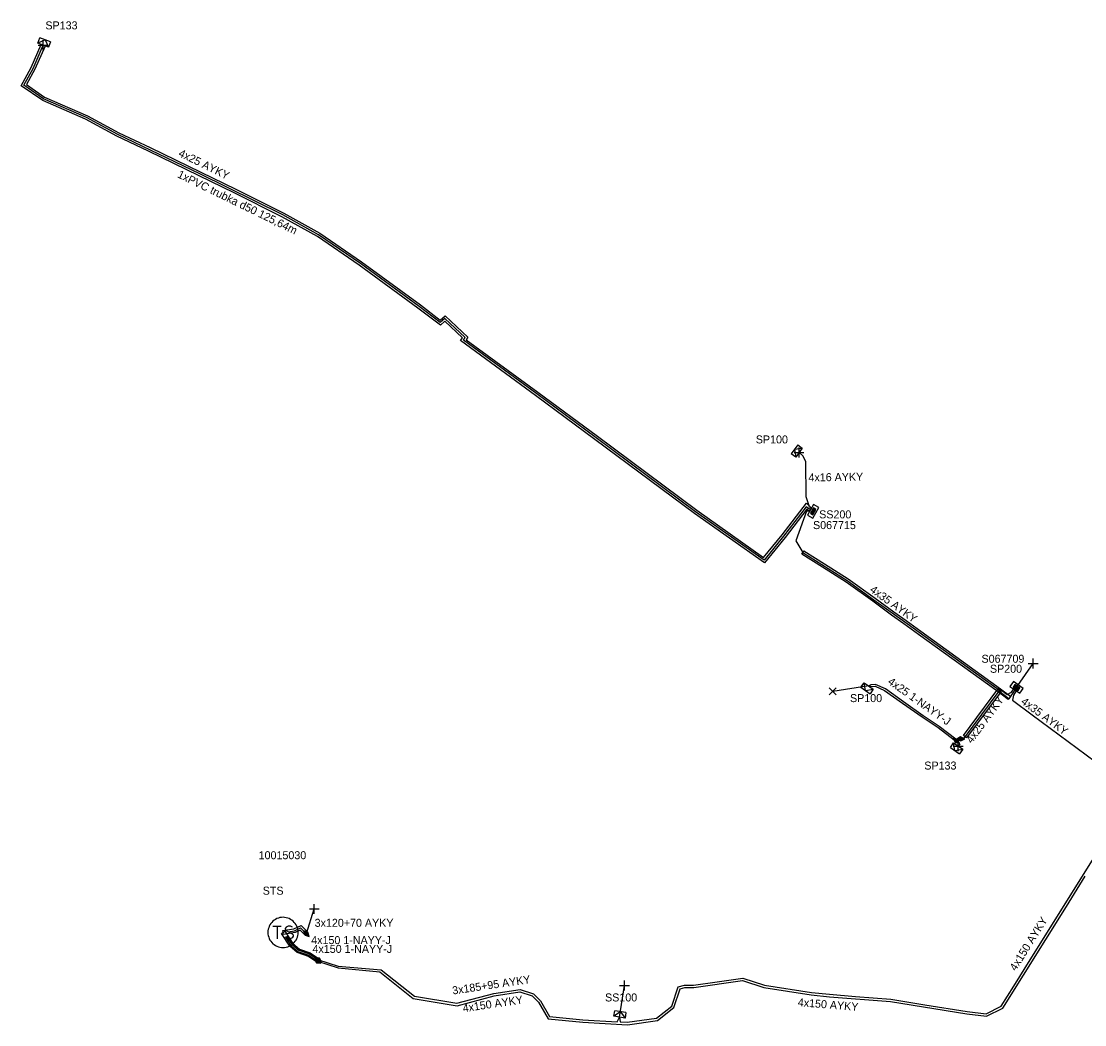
# Model space of a CAD drawing. Extents: x -737417 to -734469, y -1145580 to -1142703.
# Drawn here: x -737058.1 to -736925.2, y -1144906.3 to -1144780.8 of the extents above; entities that cross this region are included whole.
import ezdxf

# ---------------------------------------------------------------- set-up
doc = ezdxf.new("R2010")
doc.units = 0
for name, color, linetype in [('Vrstva 1', 7, 'Continuous'), ('Vrstva 19', 7, 'Continuous'), ('Vrstva 20', 7, 'Continuous'), ('Vrstva 21', 7, 'Continuous'), ('Vrstva 25', 7, 'Continuous'), ('Vrstva 26', 7, 'Continuous'), ('Vrstva 27', 7, 'Continuous'), ('Vrstva 28', 7, 'Continuous'), ('Vrstva 29', 7, 'Continuous'), ('Vrstva 30', 7, 'Continuous'), ('Vrstva 31', 7, 'Continuous'), ('Vrstva 33', 7, 'Continuous'), ('Vrstva 34', 7, 'Continuous'), ('Vrstva 4', 7, 'Continuous'), ('Vrstva 5', 7, 'Continuous'), ('Vrstva 52', 7, 'Continuous'), ('Vrstva 54', 7, 'Continuous'), ('Vrstva 59', 7, 'Continuous'), ('Vrstva 6', 7, 'Continuous'), ('Vrstva 8', 7, 'Continuous'), ('Vrstva 9', 7, 'Continuous')]:
    doc.layers.add(name, color=color, linetype=linetype)

# ---------------------------------------------------------------- blocks, each defined once
blk = doc.blocks.new('NN870')
at = {"layer": 'Vrstva 4'}
for points in [[(0, -0.25), (0.5, 0), (0, 0.25), (-0.5, 0), (0, -0.25)], [(0.37, 0), (0, 0.19), (-0.36, 0), (0, -0.19), (0.37, 0)], [(0.24, 0), (0, 0.12), (-0.25, 0), (0, -0.12), (0.24, 0)], [(0.12, 0), (0, 0.06), (-0.13, 0), (0, -0.06), (0.12, 0)]]:
    blk.add_lwpolyline(points, dxfattribs=at)
blk = doc.blocks.new('NN800')
at = {"layer": 'Vrstva 1'}
for points in [[(-0.44, 0.44), (0.44, -0.44)], [(-0.44, -0.44), (0.44, 0.44)]]:
    blk.add_lwpolyline(points, dxfattribs=at)
blk = doc.blocks.new('NN620')
at = {"layer": 'Vrstva 8'}
for points in [[(0.75, 0), (-0.75, 0)], [(-0.75, 0), (-0.75, -0.75)], [(0.75, -0.75), (0.75, 0)], [(-0.75, -0.75), (0.75, -0.75)], [(0.37, -0.18), (-0.38, -0.18)], [(-0.38, -0.18), (-0.38, -0.56)], [(-0.38, -0.56), (0.37, -0.56)], [(0.32, -0.23), (-0.33, -0.23)], [(-0.33, -0.23), (-0.33, -0.51)], [(-0.33, -0.51), (0.32, -0.51)], [(0.27, -0.27), (-0.28, -0.27)], [(-0.28, -0.27), (-0.28, -0.46)], [(-0.28, -0.46), (0.27, -0.46)], [(0.23, -0.32), (-0.23, -0.32)], [(-0.23, -0.32), (-0.23, -0.42)], [(-0.23, -0.42), (0.23, -0.42)], [(-0.19, -0.37), (0.19, -0.37)], [(0.23, -0.42), (0.23, -0.32)], [(0.27, -0.46), (0.27, -0.27)], [(0.32, -0.51), (0.32, -0.23)], [(0.37, -0.56), (0.37, -0.18)]]:
    blk.add_lwpolyline(points, dxfattribs=at)
blk = doc.blocks.new('NN630')
at = {"layer": 'Vrstva 9'}
for points in [[(0, -0.7), (-0.7, 0)], [(-0.7, -0.7), (-0.7, 0), (0.7, 0), (0.7, -0.7)], [(-0.7, -0.7), (0.7, -0.7)], [(0, -0.7), (0.7, 0)]]:
    blk.add_lwpolyline(points, dxfattribs=at)
blk = doc.blocks.new('NN610')
at = {"layer": 'Vrstva 6'}
for points in [[(1.88, 0), (1.87, 0.2), (1.84, 0.39), (1.79, 0.58), (1.72, 0.77), (1.63, 0.94), (1.52, 1.11), (1.4, 1.26), (1.26, 1.4), (1.1, 1.53), (0.94, 1.63), (0.76, 1.72), (0.58, 1.8), (0.19, 1.88), (0.19, 1.88), (-0.01, 1.89), (-0.21, 1.88), (-0.4, 1.85), (-0.59, 1.8), (-0.78, 1.72), (-0.95, 1.63), (-1.12, 1.53), (-1.27, 1.4), (-1.41, 1.26), (-1.54, 1.11), (-1.64, 0.94), (-1.73, 0.77), (-1.8, 0.58), (-1.86, 0.39), (-1.89, 0.2), (-1.9, 0), (-1.89, -0.2), (-1.86, -0.39), (-1.8, -0.58), (-1.73, -0.77), (-1.64, -0.95), (-1.54, -1.11), (-1.41, -1.27), (-1.27, -1.41), (-1.12, -1.53), (-0.95, -1.64), (-0.78, -1.73), (-0.59, -1.8), (-0.4, -1.85), (-0.21, -1.88), (-0.01, -1.89), (0.19, -1.88), (0.39, -1.85), (0.58, -1.8), (0.76, -1.73), (0.94, -1.64), (1.1, -1.53), (1.26, -1.41), (1.4, -1.27), (1.52, -1.11), (1.63, -0.95), (1.72, -0.77), (1.79, -0.58), (1.84, -0.39), (1.87, -0.2), (1.88, 0)], [(-1.27, 0.78), (-0.26, 0.78)], [(-0.76, 0.78), (-0.76, -0.79)], [(1.19, 0.66), (0.94, 0.78), (0.62, 0.78), (0.37, 0.66), (0.24, 0.47), (0.24, 0.4), (0.37, 0.22), (1.12, -0.16), (1.25, -0.32), (1.25, -0.48), (1.12, -0.67), (0.87, -0.79), (0.62, -0.79), (0.49, -0.73), (0.24, -0.6)]]:
    blk.add_lwpolyline(points, dxfattribs=at)

msp = doc.modelspace()

# ---------------------------------------------------------------- linework, layer by layer
at = {"layer": 'Vrstva 20'}
for points in [[(-736959.58, -1144842.09), (-736959.88, -1144841.81), (-736962.58, -1144845.36), (-736965.18, -1144848.54), (-736973.94, -1144842.35), (-736986.36, -1144833.11), (-736993.8, -1144827.6), (-737003.15, -1144820.76), (-737002.92, -1144820.42), (-737005.12, -1144818.34), (-737005.69, -1144818.83), (-737008.49, -1144816.69), (-737015.82, -1144811.32), (-737021.03, -1144807.75), (-737025.51, -1144805.27), (-737031.45, -1144802.28), (-737035.85, -1144800.14), (-737042.18, -1144797.06), (-737046.11, -1144795.22), (-737050.02, -1144793.09), (-737055.39, -1144790.75), (-737058.07, -1144788.91), (-737056.83, -1144786.62), (-737055.56, -1144783.73), (-737055.1, -1144783.93), (-737056.38, -1144786.84), (-737057.41, -1144788.75), (-737055.15, -1144790.31), (-737049.8, -1144792.65), (-737045.89, -1144794.78), (-737041.96, -1144796.6), (-737035.63, -1144799.69), (-737031.23, -1144801.84), (-737025.27, -1144804.83), (-737020.77, -1144807.33), (-737015.53, -1144810.92), (-737008.19, -1144816.29), (-737005.71, -1144818.19), (-737005.1, -1144817.68), (-737002.26, -1144820.34), (-737002.47, -1144820.64), (-736993.5, -1144827.2), (-736986.06, -1144832.71), (-736973.64, -1144841.95), (-736965.28, -1144847.86), (-736962.98, -1144845.05), (-736959.94, -1144841.07), (-736959.24, -1144841.73)], [(-736960.52, -1144847.47), (-736960.26, -1144847.05), (-736957.67, -1144848.67), (-736954.7, -1144850.54), (-736951.36, -1144852.94), (-736949, -1144854.66), (-736947.45, -1144855.76), (-736945.62, -1144857.1), (-736935.66, -1144864.27), (-736934.4, -1144865.24), (-736934.7, -1144865.64), (-736935.96, -1144864.67), (-736945.91, -1144857.51), (-736947.74, -1144856.17), (-736949.29, -1144855.07), (-736951.65, -1144853.34), (-736954.98, -1144850.96), (-736957.94, -1144849.09)], [(-736939.91, -1144870.42), (-736940.31, -1144870.12), (-736936.01, -1144864.32), (-736935.61, -1144864.62)], [(-737025.13, -1144894.6), (-737024.11, -1144896.13), (-737023.31, -1144896.83), (-737021.96, -1144897.28), (-737020.84, -1144898.04), (-737021.12, -1144898.46), (-737022.18, -1144897.74), (-737023.57, -1144897.27), (-737024.49, -1144896.47), (-737025.55, -1144894.88)], [(-737025.38, -1144894.49), (-737023.98, -1144894.29), (-737023.1, -1144893.86), (-737022.24, -1144894.71), (-737022.6, -1144895.07), (-737023.2, -1144894.46), (-737023.82, -1144894.77), (-737025.3, -1144894.99)]]:
    msp.add_lwpolyline(points, close=True, dxfattribs=at)
at = {"layer": 'Vrstva 5'}
for points in [[(-736959.51, -1144842.09), (-736959.91, -1144842.09), (-736961.24, -1144845.8), (-736960.39, -1144847.26), (-736954.84, -1144850.75), (-736951.52, -1144853.15), (-736947.36, -1144856.14), (-736936.11, -1144864.25), (-736935.72, -1144864.35), (-736934.86, -1144865.01), (-736934.32, -1144864.69), (-736934.01, -1144864.31)], [(-736940.65, -1144870.56), (-736941.26, -1144870.58), (-736943.34, -1144868.98), (-736945.34, -1144867.65), (-736947.79, -1144865.92), (-736950.06, -1144864.3), (-736951.3, -1144863.74), (-736951.87, -1144863.8), (-736952.14, -1144863.93), (-736951.73, -1144863.98), (-736951.34, -1144863.94), (-736950.16, -1144864.48), (-736947.91, -1144866.08), (-736945.46, -1144867.81), (-736943.46, -1144869.14), (-736941.48, -1144870.66), (-736941.19, -1144870.79)], [(-736933.88, -1144864.42), (-736934.64, -1144865.56), (-736935.9, -1144864.59), (-736940.21, -1144870.42), (-736940.65, -1144870.56)], [(-736933.7, -1144864.52), (-736934.04, -1144865.07), (-736934.19, -1144865.71), (-736931.73, -1144867.53), (-736921.6, -1144875.04), (-736919.22, -1144874.32), (-736920.26, -1144873.68)], [(-736983.3, -1144905.34), (-736983.2, -1144905.93), (-736982.33, -1144905.98), (-736978.66, -1144905.48), (-736976.75, -1144903.94), (-736975.96, -1144901.54), (-736975.18, -1144901.33), (-736974.04, -1144901.32), (-736971.1, -1144900.91), (-736967.89, -1144900.45), (-736965.19, -1144901.34), (-736959.29, -1144902.26), (-736957.04, -1144902.48), (-736953.8, -1144902.74), (-736949.38, -1144903.09), (-736945.14, -1144903.78), (-736939.83, -1144904.63), (-736937.49, -1144904.9), (-736935.59, -1144903.96), (-736934.03, -1144901.45), (-736931.98, -1144898.17), (-736923.56, -1144884.72)], [(-737021.04, -1144898.33), (-737018.47, -1144899.18), (-737013.27, -1144899.65), (-737009.1, -1144902.99), (-737003.6, -1144903.9), (-736998.95, -1144902.66), (-736995.75, -1144902.18), (-736994.21, -1144902.67), (-736993.43, -1144903.48), (-736992.21, -1144905.55), (-736987.88, -1144905.98), (-736982.31, -1144906.28), (-736978.54, -1144905.76), (-736976.49, -1144904.12), (-736975.72, -1144901.78), (-736975.14, -1144901.63), (-736974.02, -1144901.62), (-736967.91, -1144900.75), (-736965.26, -1144901.64), (-736959.33, -1144902.56), (-736957.06, -1144902.78), (-736949.42, -1144903.39), (-736939.87, -1144904.93), (-736937.43, -1144905.2), (-736935.38, -1144904.19), (-736927.44, -1144891.48), (-736925.09, -1144887.72)], [(-737024.69, -1144894.65), (-737023.9, -1144894.53), (-737023.15, -1144894.16), (-737022.42, -1144894.89)], [(-737025.06, -1144895.34), (-737024.38, -1144896.37), (-737023.49, -1144897.14), (-737022.11, -1144897.6), (-737021.04, -1144898.33)], [(-737024.9, -1144895.22), (-737024.22, -1144896.23), (-737023.39, -1144896.96), (-737022.03, -1144897.42), (-737020.92, -1144898.17)], [(-737020.92, -1144898.17), (-737018.44, -1144898.95), (-737013.08, -1144899.4), (-737008.94, -1144902.71), (-737003.62, -1144903.6), (-736999.01, -1144902.36), (-736995.73, -1144901.88), (-736994.05, -1144902.41), (-736993.19, -1144903.3), (-736992.03, -1144905.27), (-736987.86, -1144905.68), (-736983.59, -1144905.9), (-736983.3, -1144905.34)]]:
    msp.add_lwpolyline(points, dxfattribs=at)
at = {"layer": 'Vrstva 52'}
for points in [[(-736959.41, -1144841.91), (-736959.97, -1144841.52), (-736962.78, -1144845.21), (-736965.23, -1144848.2), (-736973.79, -1144842.15), (-736986.21, -1144832.91), (-736993.65, -1144827.4), (-737002.81, -1144820.7), (-737002.59, -1144820.38), (-737005.11, -1144818.01), (-737005.7, -1144818.51), (-737008.34, -1144816.49), (-737015.67, -1144811.12), (-737020.9, -1144807.54), (-737025.39, -1144805.05), (-737035.74, -1144799.91), (-737046, -1144795), (-737049.91, -1144792.87), (-737055.27, -1144790.53), (-737057.74, -1144788.83), (-737056.6, -1144786.73), (-737055.33, -1144783.83)], [(-736959.29, -1144841.77), (-736959.54, -1144841.53), (-736959.95, -1144840.27), (-736960.02, -1144835.88), (-736960.38, -1144835.18), (-736960.86, -1144834.75)], [(-736941.19, -1144870.79), (-736940.77, -1144871.17), (-736940.97, -1144871.44)]]:
    msp.add_lwpolyline(points, dxfattribs=at)
at = {"layer": 'Vrstva 59'}
for points in [[(-736933.5, -1144863.87), (-736931.61, -1144861.13)], [(-736952.14, -1144863.93), (-736956.65, -1144864.62)], [(-737022.42, -1144894.89), (-737021.44, -1144891.81)], [(-736983.3, -1144905.34), (-736982.66, -1144901.39)]]:
    msp.add_lwpolyline(points, dxfattribs=at)

# ---------------------------------------------------------------- block references
at = {"layer": 'Vrstva 19'}
for p, rotation in [((-736941.19, -1144870.79), -37.77717136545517), ((-736940.65, -1144870.56), 3.47376526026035), ((-737022.42, -1144894.89), -45.282485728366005), ((-737020.95, -1144898.15), -34.923701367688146), ((-737021.04, -1144898.33), -32.93533191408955)]:
    msp.add_blockref('NN870', p, dxfattribs=dict(at, rotation=rotation))
at = {"layer": 'Vrstva 25'}
msp.add_blockref('NN610', (-737025.34, -1144894.74), dxfattribs=at)
at = {"layer": 'Vrstva 28'}
for p, rotation in [((-736959.41, -1144841.91), 60.12400841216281), ((-736933.88, -1144864.42), 145.43059169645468)]:
    msp.add_blockref('NN620', p, dxfattribs=dict(at, rotation=rotation))
at = {"layer": 'Vrstva 31'}
for p, rotation in [((-737055.33, -1144783.83), 159.20128886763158), ((-736960.86, -1144834.75), -126.19320829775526), ((-736952.14, -1144863.93), -35.90344366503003), ((-736940.97, -1144871.44), -34.53349169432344), ((-736983.3, -1144905.34), 170.8518527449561)]:
    msp.add_blockref('NN630', p, dxfattribs=dict(at, rotation=rotation))
at = {"layer": 'Vrstva 34'}
for p, rotation in [((-737055.33, -1144783.83), 45), ((-736960.86, -1144834.75), 45), ((-736931.61, -1144861.13), 45), ((-736940.97, -1144871.44), 45.00000009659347), ((-737021.44, -1144891.81), 45), ((-736982.66, -1144901.39), 45)]:
    msp.add_blockref('NN800', p, dxfattribs=dict(at, rotation=rotation))
msp.add_blockref('NN800', (-736956.65, -1144864.62), dxfattribs=at)

# ---------------------------------------------------------------- texts
at = {"layer": 'Vrstva 21'}
msp.add_text('1xPVC trubka d50 125,64m', height=1, rotation=333.958, dxfattribs=at).set_placement((-737038.64, -1144800.31))
at = {"layer": 'Vrstva 26'}
msp.add_text('10015030', height=1, dxfattribs=at).set_placement((-737028.4, -1144885.59))
at = {"layer": 'Vrstva 27'}
msp.add_text('STS', height=1, dxfattribs=at).set_placement((-737027.89, -1144890.02))
at = {"layer": 'Vrstva 29'}
for s, p in [('S067715', (-736959.11, -1144844.32)), ('S067709', (-736938.05, -1144861.03))]:
    msp.add_text(s, height=1, dxfattribs=at).set_placement(p)
at = {"layer": 'Vrstva 30'}
for s, p in [('SS200', (-736958.34, -1144842.98)), ('SP200', (-736937, -1144862.28))]:
    msp.add_text(s, height=1, dxfattribs=at).set_placement(p)
at = {"layer": 'Vrstva 33'}
for s, p in [('SP133', (-737055.05, -1144781.85)), ('SP100', (-736966.26, -1144833.61)), ('SP100', (-736954.49, -1144865.95)), ('SP133', (-736945.2, -1144874.38)), ('SS100', (-736985.1, -1144903.37))]:
    msp.add_text(s, height=1, dxfattribs=at).set_placement(p)
at = {"layer": 'Vrstva 54'}
for s, rotation, p in [('4x25 AYKY', 333.964, (-737038.51, -1144797.66)), ('4x16 AYKY', 0.914, (-736959.67, -1144838.37))]:
    msp.add_text(s, height=1, rotation=rotation, dxfattribs=at).set_placement(p)
at = {"layer": 'Vrstva 6'}
for s, rotation, p in [('4x35 AYKY', 324.293, (-736952.1, -1144852.09)), ('4x25 1-NAYY-J', 324.762, (-736949.86, -1144863.59)), ('4x25 AYKY', 53.508, (-736939.27, -1144871.19)), ('4x35 AYKY', 323.448, (-736933.21, -1144866.07)), ('4x150 AYKY', 57.96, (-736933.77, -1144899.64)), ('3x185+95 AYKY', 8.422, (-737004.12, -1144902.51)), ('4x150 AYKY', 8.43, (-737002.82, -1144904.72)), ('4x150 AYKY', 355.438, (-736961.04, -1144903.95))]:
    msp.add_text(s, height=1, rotation=rotation, dxfattribs=at).set_placement(p)
for s, p in [('3x120+70 AYKY', (-737021.4, -1144894.04)), ('4x150 1-NAYY-J', (-737021.83, -1144896.2)), ('4x150 1-NAYY-J', (-737021.67, -1144897.3))]:
    msp.add_text(s, height=1, dxfattribs=at).set_placement(p)

doc.saveas('drawing.dxf')
